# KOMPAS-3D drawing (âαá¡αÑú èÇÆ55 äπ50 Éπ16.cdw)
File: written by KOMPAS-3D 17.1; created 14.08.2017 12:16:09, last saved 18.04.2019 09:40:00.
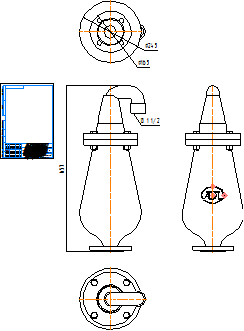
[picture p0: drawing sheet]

Sheet 1: A4, portrait

Title block, sheet 1: name: Гранрег КАТ55 Ду50 Ру16; material: Внимание! Данный продукт является объектом авторского права ООО «Торговый Дом АДЛ». / Запрещается изменение, копирование, распространение / (в том числе путем копирования на другие сайты и ресурсы в Интернете) / или любое иное использование информации и объектов без предварительного / согласия правообладателя (ООО «Торговый Дом АДЛ»).; mass: 116,3; sheets: 1; organisation: ООО "Торговый дом АДЛ"; sheet format: A4; stored path: \\adlc.lan\data\АДЛ_ПКД\3D-модели\ADL production\Клапаны КАТ ГРАНРЕГ\КАТ55\KOMPAS 2D\Гранрег КАТ55 Ду50 Ру16.cdw

Views: Вид 1, Проекционный вид 2, Проекционный вид 3, Проекционный вид 4, Проекционный вид 5
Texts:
  kka
  adl
Dimensions and other numbers on the sheet: 657; 245; 165; 1:1; 1; 116,3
